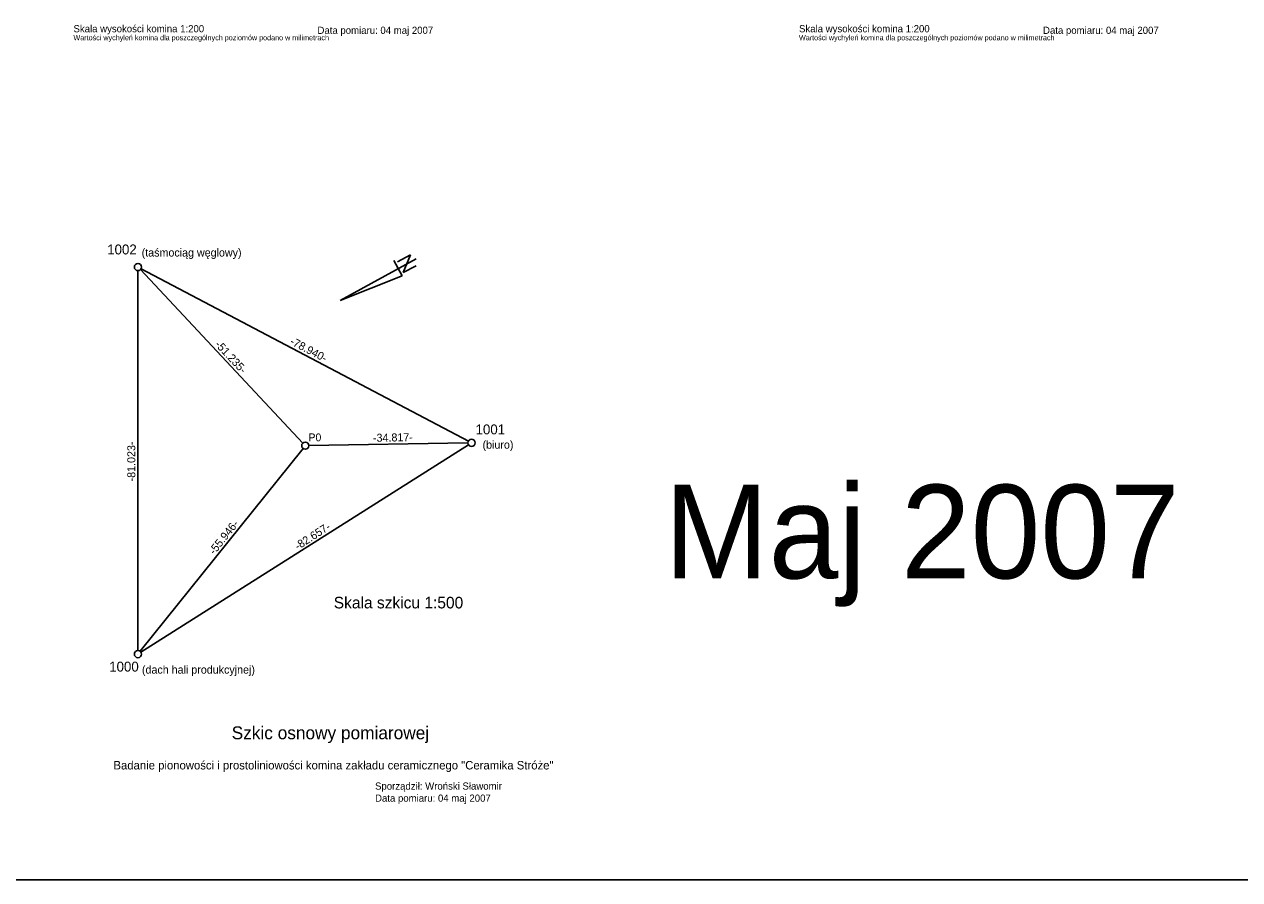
# Model space of a CAD drawing. Extents: x 138 to 6653, y -177 to 1520.
# Drawn here: x 196.6 to 248.8, y 47.8 to 84.5 of the extents above; entities that cross this region are included whole.
import ezdxf

# ---------------------------------------------------------------- set-up
doc = ezdxf.new("R2010")
doc.units = 0
for name, color, linetype in [('15 listopad 2008', 7, 'Continuous'), ('Default', 7, 'Continuous'), ('Opisy', 7, 'Continuous'), ('Standard', 7, 'Continuous')]:
    doc.layers.add(name, color=color, linetype=linetype)

msp = doc.modelspace()

# ---------------------------------------------------------------- linework, layer by layer
at = {"layer": '15 listopad 2008'}
msp.add_lwpolyline([(139.203, 110.337), (257.14, 110.337), (257.14, 47.785), (139.203, 47.785)], close=True, dxfattribs=at)
at = {"layer": 'Standard'}
for p, q in [((213.19, 74.583), (212.633, 74.286)), ((212.88, 73.823), (213.19, 74.583)), ((201.503, 74.063), (201.503, 74.063)), ((213.429, 74.415), (210.173, 72.634)), ((212.829, 73.679), (212.481, 74.337)), ((213.437, 74.12), (212.88, 73.823)), ((201.503, 73.909), (201.503, 69.047)), ((201.608, 73.951), (208.573, 66.513)), ((201.639, 73.991), (215.675, 66.593)), ((210.173, 72.634), (212.829, 73.679)), ((201.503, 69.047), (201.503, 67.567)), ((201.503, 67.567), (201.503, 57.616)), ((208.582, 66.281), (201.599, 57.582)), ((215.681, 66.439), (201.632, 57.544)), ((208.832, 66.403), (215.657, 66.519)), ((215.811, 66.522), (215.811, 66.522)), ((201.503, 57.462), (201.503, 57.462))]:
    msp.add_line(p, q, dxfattribs=at)
for centre in [(201.503, 74.063), (208.679, 66.401), (215.811, 66.522), (201.503, 57.462)]:
    msp.add_circle(centre, 0.154, dxfattribs=at)

# ---------------------------------------------------------------- texts
at = {"layer": 'Default'}
msp.add_text('Maj 2007', height=4.0171, dxfattribs=at).set_placement((224.08, 60.708))
at = {"layer": 'Opisy'}
for s, height, p in [('Skala wysokości komina 1:200', 0.30766, (198.739, 84.132)), ('Skala wysokości komina 1:200', 0.30766, (229.853, 84.132)), ('Wartości wychyleń komina dla poszczególnych poziomów podano w milimetrach', 0.22315, (198.736, 83.789)), ('Data pomiaru: 04 maj 2007', 0.30766, (209.202, 84.064)), ('Wartości wychyleń komina dla poszczególnych poziomów podano w milimetrach', 0.22315, (229.85, 83.789)), ('Data pomiaru: 04 maj 2007', 0.30766, (240.316, 84.064))]:
    msp.add_text(s, height=height, dxfattribs=at).set_placement(p)
at = {"layer": 'Standard'}
for s, height, p in [('1002', 0.426, (200.184, 74.604)), ('(taśmociąg węglowy)', 0.34308, (201.663, 74.513)), ('1001', 0.426, (215.981, 66.886)), ('P0', 0.3382, (208.814, 66.588)), ('(biuro)', 0.3431, (216.281, 66.273)), ('Skala szkicu 1:500', 0.49797, (209.9, 59.421)), ('1000', 0.426, (200.27, 56.711)), ('(dach hali produkcyjnej)', 0.34308, (201.675, 56.624)), ('Szkic osnowy pomiarowej', 0.55314, (205.523, 53.809)), ('Badanie pionowości i prostoliniowości komina zakładu ceramicznego "Ceramika Stróże"', 0.36281, (200.453, 52.514)), ('Sporządził: Wroński Sławomir', 0.30766, (211.671, 51.647)), ('Data pomiaru: 04 maj 2007', 0.30766, (211.671, 51.13))]:
    msp.add_text(s, height=height, dxfattribs=at).set_placement(p)
for s, rotation, p in [('-78.940-', 332.128, (207.99, 70.772)), ('-51.235-', 313.1874, (204.781, 70.716)), ('-34.817-', 1.0923, (211.586, 66.565)), ('-81.023-', 90, (201.389, 64.869)), ('-55.946-', 51.3924, (204.78, 61.702)), ('-82.657-', 32.8285, (208.359, 61.913))]:
    msp.add_text(s, height=0.3431, rotation=rotation, dxfattribs=at).set_placement(p)

doc.saveas('drawing.dxf')
